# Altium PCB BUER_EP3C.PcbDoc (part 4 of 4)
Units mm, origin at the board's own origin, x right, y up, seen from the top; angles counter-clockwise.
Board outline 150 x 80 mm, 2 copper layers (Top Layer, Bottom Layer), stack 1.571 mm thick; 295 components, 180 nets, 1344 pads, 488 vias.
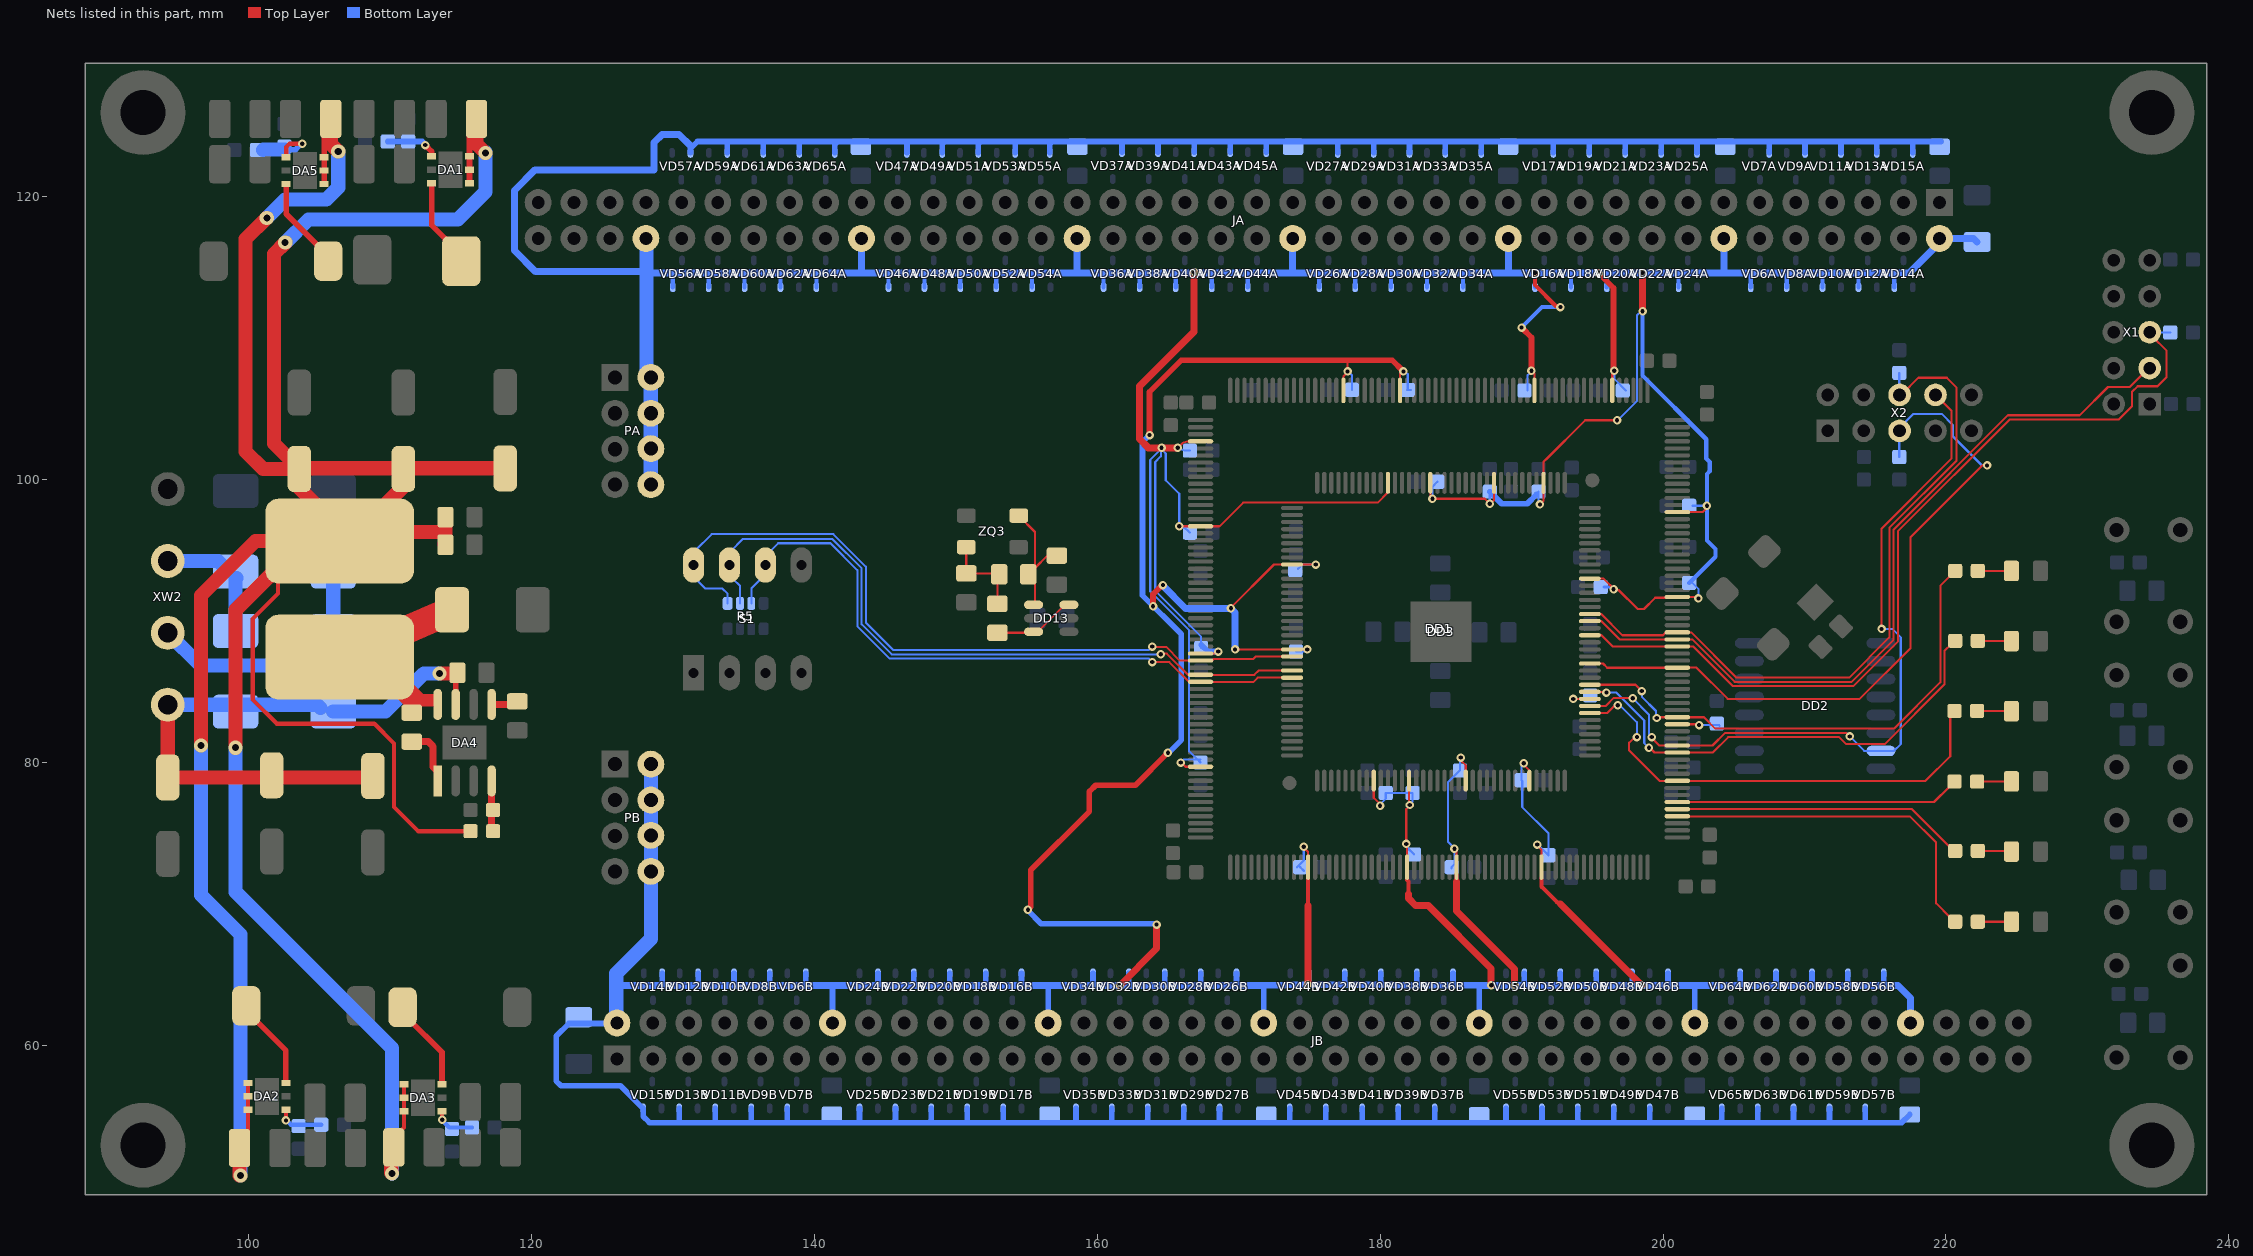
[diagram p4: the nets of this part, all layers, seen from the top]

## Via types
v1: diameter 0.6, hole 0.3, Top Layer to Bottom Layer, tented both sides, 413 vias
v2: diameter 1.4, hole 0.7, Top Layer to Bottom Layer, 32 vias
v3: diameter 1, hole 0.5, Top Layer to Bottom Layer, tented both sides, 19 vias
v4: diameter 0.66, hole 0.33, Top Layer to Bottom Layer, tented top, 16 vias
v5: diameter 0.6, hole 0.3, Top Layer to Bottom Layer, 8 vias

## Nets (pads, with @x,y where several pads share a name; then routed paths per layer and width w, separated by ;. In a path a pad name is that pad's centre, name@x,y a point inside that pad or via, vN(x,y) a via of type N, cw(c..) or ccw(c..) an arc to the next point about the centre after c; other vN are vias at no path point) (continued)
JTAG.TDO: DD1.29 DD3.20 X1.3 | length 54.2
  Top Layer w0.15: DD3.20@194.825,90 195.65,90 196.95,88.7 DD1.29@200.45,88.7 ; DD1.29@201.006,88.707 202.057,88.707 205.064,85.7 213.327,85.7 216.3,88.673 216.3,96.473 224.377,104.55 229.45,104.55 231.45,106.55 233,106.55 X1.3@234.1,107.65
JTAG.TMS: DD1.28 DD3.18 R2.1 X1.5 | length 60.6
  Top Layer w0.15: DD3.18@194.825,89 195.65,89 196.45,88.2 DD1.28@200.3,88.2 ; DD1.28@201.006,88.207 202.133,88.207 204.94,85.4 213.451,85.4 216.6,88.549 216.6,96.349 224.501,104.25 232.22,104.25 233.15,105.18 233.15,106.2 233.55,106.6 234.95,106.6 235.6,107.25 235.6,109.1 X1.5@234.55,110.15
  Bottom Layer w0.15: X1.5@234.4,110.35 234.45,110.4 R2.1@235.85,110.4
LED0: DD1.18 DD3.11 R24.2 | length 35.6
  Top Layer w0.15: DD3.11@194.825,85.5 198.05,85.5 198.3,85.25 198.3,85.1 v1@198.4,85.2 ; v1@199.607,83.207 DD1.18@201.006,83.207 202.89,83.207 203.697,82.4 216.321,82.4 219.6,85.679 219.6,92.5 R24.2@220.3,93.2
  Bottom Layer w0.15: v1(198.5,85.05) 198.5,84.643 199.5,83.642 v1@199.5,83.25
  other v1: 199.55,83.15
LED1: DD1.13 DD3.10 R25.2 | length 33.3
  Top Layer w0.15: DD3.10@194.825,85 195.95,85 v1(196,84.95) ; v1@198.975,81.125 199.025,81.075 199.393,80.707 DD1.13@201.006,80.707 203.507,80.707 204.6,81.8 212.45,81.8 212.925,81.325 215.696,81.325 219.9,85.529 219.9,87.9 R25.2@220.4,88.4
  Bottom Layer w0.15: v1(196,84.95) 196.7,84.95 198.675,82.975 198.675,81.375 v1(199,81.05)
LED2: DD1.9 DD3.7 R26.2 | length 33.6
  Top Layer w0.15: DD3.7@194.825,83.5 196.05,83.5 196.55,84 v1@196.8,84 ; v1@198.1,81.8 198,81.8 197.6,81.4 197.6,80.858 199.751,78.707 DD1.9@201.006,78.707 218.557,78.707 220.3,80.45 R26.2@220.3,83.45
  Bottom Layer w0.15: v1(196.8,84.05) 196.95,84.05 198.15,82.85 v1(198.15,81.8)
LED3: DD1.6 R27.2 | length 19.7
  Top Layer w0.15: DD1.6@201.006,77.207 219.157,77.207 220.25,78.3 R27.2@220.25,78.25
LED4: DD1.5 R28.2 | length 20.7
  Top Layer w0.15: DD1.5@201.006,76.707 217.593,76.707 220.3,74 R28.2@220.6,74
LED5: DD1.4 R29.2 | length 24.8
  Top Layer w0.15: DD1.4@201.006,76.207 201.013,76.2 217.45,76.2 219.3,74.35 219.3,70.05 R29.2@220.3,69.05
MSEL0: DD1.155 DD3.94 R5.1 S1.8 | length 51.1
  Top Layer w0.15: v1@163.9,88 164.075,88.175 164.875,88.175 165.843,87.207 DD1.155@167.306,87.207 ; DD1.155@168.1,87.2 168.225,87.325 171.025,87.325 171.2,87.5 173.25,87.5 DD3.94@173.3,87.55
  Bottom Layer w0.15: S1.8@131.55,94.95 132.75,96.15 141.35,96.15 143.65,93.85 143.65,89.9 145.6,87.95 163.65,87.95 v1(163.9,88.2) ; S1.8@131.7,92.9 132.3,92.3 133.5,92.3 133.875,91.925 R5.1@133.875,91.25
MSEL1: DD1.157 DD3.96 R5.2 S1.7 | length 47.8
  Top Layer w0.15: v1@164.55,87.7 164.926,87.7 166.419,86.207 DD1.157@167.306,86.207 ; DD1.157@167.95,86.2 171.1,86.2 171.4,86.5 DD3.96@173.775,86.5
  Bottom Layer w0.15: S1.7@134.05,94.9 134.95,95.8 141.276,95.8 143.35,93.726 143.35,89.776 145.476,87.65 v1(164.5,87.65) ; S1.7@134.25,93 134.75,92.5 R5.2@134.75,91.25
MSEL2: DD1.158 DD3.97 R5.3 S1.6 | length 45.3
  Top Layer w0.15: v1@163.85,87.1 165.1,87.1 166.493,85.707 DD1.158@167.306,85.707 171.057,85.707 171.35,86 DD3.97@173.2,86
  Bottom Layer w0.15: R5.3@135.55,91.25 135.55,92.3 S1.6@136.2,92.95 ; S1.6@136.75,94.8 137.45,95.5 141.151,95.5 143.05,93.601 143.05,89.624 145.324,87.35 163.65,87.35 v1(163.9,87.1)
NCE: DD1.30 DD3.21 R16.2 X2.6 | length 49.7
  Top Layer w0.15: DD3.21@194.825,90.5 195.626,90.5 197.126,89 200,89 DD1.30@200.2,89.2 ; DD1.30@201.006,89.207 201.981,89.207 205.188,86 213.15,86 216,88.85 216,96.597 220.75,101.347 220.75,106.5 220.05,107.2 218.05,107.2 X2.6@216.9,106.05
  Bottom Layer w0.15: R16.2@216.7,107.55 216.7,105.8 X2.6@216.8,105.7
NCONFIG: DD1.25 DD3.14 R15.1 X2.5 | length 49.5
  Top Layer w0.15: DD3.14@194.825,87 195.75,87 196.05,86.7 DD1.25@200.25,86.7 ; DD1.25@201.006,86.707 202.36,86.707 204.567,84.5 213.9,84.5 217.5,88.1 217.5,95.942 222.558,101 v1(222.9,101)
  Bottom Layer w0.15: R15.1@216.7,101.6 216.7,103.05 X2.5@216.8,103.15 ; X2.5@217.05,104 217.7,104.65 219.7,104.65 220.5,103.85 220.5,103.05 222.55,101 v1(222.9,101)
NCS: DD1.14 DD2.7 DD3.8 X2.8 | length 53.5
  Top Layer w0.15: DD3.8@194.825,84 195.95,84 196.525,84.575 197.825,84.575 v1(197.85,84.55) ; v1@199.175,81.775 199.743,81.207 DD1.14@201.006,81.207 203.499,81.207 204.392,82.1 212.95,82.1 v1@213.175,81.875 ; v1@215.45,89.7 215.45,96.55 220.4,101.5 220.4,104.85 X2.8@219.26,105.99
  Bottom Layer w0.15: v1(197.85,84.55) 199,83.4 199,81.95 v1@199.15,81.8 ; v1(213.2,81.85) 214.225,80.825 DD2.7@215.4,80.825 216.325,80.825 216.8,81.3 216.8,88.85 216.2,89.45 v1@215.35,89.45
  other v1: 199.2,81.8 215.45,89.45
NetC60_1: C60.1 DA4.1 | length 3.4
  Top Layer w0.5: C60.1@111.55,81.475 112.725,81.475 113.05,81.15 113.05,79.7 DA4.1@113.3,79.45
NetC60_2: C60.2 DA4.8 L6.1 VD5.2 | length 15.2
  Top Layer w0.3: L6.1@110.9,85.4 112.19,84.11 DA4.8@113.38,84.11 DA4.8@113.2,84.29 ; L6.1@111.4,85.2 112.075,84.525 ; L6.1@111.6,85.4 112.3,84.7 113.05,84.7 113.2,84.55 DA4.8@113.2,84.29 ; 112.55,84.5 112.525,84.525 112.075,84.525 ; 112.075,84.525 112.2,84.4 113.09,84.4 DA4.8@113.2,84.29
  Top Layer w1: L6.1@109.85,85.9 111.55,84.2 C60.2@111.55,83.525
  Top Layer w2: L6.1@110.75,89.2 VD5.2@114.4,90.8
NetC68_1: C68.1 DA4.5 | length 1.7
  Top Layer w0.5: DA4.5@117.19,84.11 118.81,84.11 C68.1@118.85,84.15
NetC83_1: C83.1 DD13.1 R35.1 ZQ3.1 | length 8.9
  Top Layer w0.15: ZQ3.1@154.45,97.45 155.6,96.3 R35.1@155.6,93.75 ; R35.1@155.45,93.6 R35.1@155.6,93.75 ; DD13.1@155.6,91.15 R35.1@155.6,93.75 ; C83.1@157.15,94.625 156.475,94.625 R35.1@155.6,93.75
NetC84_1: C84.1 R34.1 R35.2 ZQ3.3 | length 6.2
  Top Layer w0.15: C84.1@150.65,93.35 150.744,93.444 ZQ3.3@150.744,95.225 ; C84.1@150.75,93.375 152.925,93.375 R35.2@153,93.3 ; R34.1@152.95,91.225 152.95,93.15 R35.2@153,93.2
NetDA1_1: DA1.1 R6.1 R7.2 | length 3.7
  Top Layer w0.4: v1(112.5,123.65) 112.95,123.2 DA1.1@112.95,122.85
  Bottom Layer w0.4: R6.1@109.85,123.9 R7.2@111.3,123.9 112.3,123.9 v1@112.5,123.7
NetDA1_3: DA1.3 L1.1 | length 4.3
  Top Layer w0.4: DA1.3@112.95,120.95 112.95,118 L1.1@113.9,117.05
NetDA2_1: DA2.1 R8.1 R9.2 | length 3.3
  Top Layer w0.3: v1@102.65,54.75 DA2.1@102.65,55.45
  Bottom Layer w0.3: v1@102.65,54.75 103,54.4 R8.1@105.15,54.4
  other v1: 102.65,54.7
NetDA2_3: DA2.3 L4.1 | length 5.5
  Top Layer w0.4: L4.1@100.4,61.9 102.65,59.65 DA2.3@102.65,57.35
NetDA3_1: DA3.1 R10.1 R11.2 | length 2.9
  Top Layer w0.3: DA3.1@113.68,55.35 113.68,54.82 v1@113.7,54.8
  Bottom Layer w0.3: v1@113.7,54.7 114.2,54.2 R10.1@115.8,54.2
  other v1: 113.7,54.75
NetDA3_3: DA3.3 L5.1 | length 5.7
  Top Layer w0.4: L5.1@111.25,61.95 113.68,59.52 DA3.3@113.68,57.25
NetDA4_4: DA4.4 R12.1 R13.2 | length 3.5
  Top Layer w0.5: R12.1@117.05,75.3 117.19,75.44 DA4.4@117.19,78.7
NetDA5_1: DA5.1 R17.1 R18.2 | length 4.8
  Top Layer w0.3: DA5.1@102.67,122.8 102.67,123.52 102.9,123.75 v1(103.8,123.75)
  Bottom Layer w0.4: R18.2@102.55,123.325 103.325,123.325 v1@103.75,123.75
  Bottom Layer w1: R17.1@101.05,123.3 101.075,123.325 R18.2@102.55,123.325
NetDA5_3: DA5.3 L2.1 | length 5.3
  Top Layer w0.4: DA5.3@102.67,120.9 102.67,118.78 L2.1@104.9,116.55
NetDD1_17: DD1.17 R3.1 | length 3.1
  Top Layer w0.15: DD1.17@201.006,82.707 202.593,82.707 v1@202.6,82.7
  Bottom Layer w0.15: v1(202.55,82.65) 203.95,82.65 R3.1@204,82.6
NetDD3_9: DD3.9 R19.1 | length 2.2
  Top Layer w0.15: v1@193.7,84.5 DD3.9@194.825,84.5
  Bottom Layer w0.15: v1(193.65,84.5) 194.65,84.5 R19.1@194.7,84.55
NetDD13_3: DD13.3 DD13.6 R34.2 | length 5.1
  Top Layer w0.15: R34.2@152.95,89.175 154.975,89.175 DD13.3@155.15,89.35 ; DD13.3@155.5,89.25 155.8,89.25 DD13.6@157.6,91.05
NetLED1_A: LED1.A R24.1 | length 2.4
  Top Layer w0.15: R24.1@222.25,93.55 224.55,93.55 LED1.A@224.6,93.5
NetLED2_A: LED2.A R25.1 | length 2.1
  Top Layer w0.15: R25.1@222.25,88.6 224.3,88.6 LED2.A@224.35,88.55
NetLED3_A: LED3.A R26.1 | length 2.2
  Top Layer w0.15: R26.1@222.2,83.65 224.25,83.65 LED3.A@224.35,83.75
NetLED4_A: LED4.A R27.1 | length 2.4
  Top Layer w0.15: R27.1@222.2,78.65 224.5,78.65 LED4.A@224.6,78.75
NetLED5_A: LED5.A R28.1 | length 2.1
  Top Layer w0.15: R28.1@222.25,73.75 224.25,73.75 LED5.A@224.35,73.65
NetLED6_A: LED6.A R29.1 | length 2.4
  Top Layer w0.15: R29.1@222.25,68.75 224.45,68.75 LED6.A@224.6,68.9
NetVD1_1: VD1.1 VD3.2 XW2.2 | length 7.9
  Bottom Layer w1: XW2.2@94.3,94.25 97.85,94.25 VD3.2@98.25,93.85 ; VD1.1@99.1,89.3 99.1,93 VD3.2@99.15,93.05
NetVD2_1: VD2.1 VD4.2 XW2.3 | length 16.1
  Bottom Layer w1: XW2.3@94.3,89.17 96.62,86.85 103.1,86.85 VD2.1@104.85,88.6 ; VD4.2@106,93.5 106,89.9 VD2.1@106.2,89.7
POWER: C57.1 C59.1 C66.1 C67.1 DA4.7 VD1.2 VD2.2 XW2.4 | length 42.5
  Top Layer w0.4: DA4.7@114.65,84.11 114.65,86.05 C67.1@114.75,86.15
  Top Layer w1: XW2.4@94.55,83.95 94.3,83.7 C59.1@94.3,78.95 108.6,78.95 C66.1@108.8,79.15 ; v3@113.6,86.3 114.725,86.3 C67.1@114.775,86.35
  Bottom Layer w1: XW2.4@94.3,84.09 104.86,84.09 VD2.2@105.1,83.85 ; VD2.2@106,83.6 109.7,83.6 112.4,86.3 v3(113.5,86.3)
VCC: C33.1 C42.1 C51.1 C54.1 C61.1 C62.1 C63.1 C64.1 C65.1 DA1.4 DA1.5 DA1.6 DA2.4 DA2.5 DA2.6 DA3.4 DA3.5 DA3.6 DA5.4 DA5.5 DA5.6 L6.2 R12.2 | length 256.9
  Top Layer w0.3: C51.1@99.75,53.8 99.97,54.02 DA2.6@99.97,55.45 DA2.5@99.97,56.4 DA2.4@99.97,57.35 ; L6.2@102.1,92.9 102.1,91.95 100.3,90.15 100.3,84.45 102,82.75 108.9,82.75 110.3,81.35 110.3,76.85 112,75.15 R12.2@115.7,75.15 ; C54.1@110.65,53.85 111,54.2 DA3.6@111,55.35 DA3.5@111,56.3 DA3.4@111,57.25
  Top Layer w0.4: DA5.4@105.35,120.9 DA5.5@105.35,121.85 DA5.6@105.35,122.8 105.35,124.8 C42.1@105.6,125.05 ; DA1.4@115.63,120.95 DA1.5@115.63,121.9 DA1.6@115.63,122.85 115.63,124.78 C33.1@115.85,125
  Top Layer w1: v3(96.65,81.2) 96.65,91.8 100.5,95.65 L6.2@103.95,95.65 ; v3(99.1,81.05) 99.1,90.8 L6.2@103.95,95.65 ; C51.1@99.375,52.75 99.375,50.8 v3(99.45,50.8) ; v3(101.3,118.5) 99.8,117 99.8,102 101.05,100.75 C63.1@103.6,100.75 101.8,102.55 101.8,115.95 v3(102.6,116.75) ; C63.1@103.45,99.55 106.45,96.55 L6.2@106.45,95.65 ; C63.1@103.55,101 103.75,100.8 C61.1@118.15,100.8 ; C42.1@105.825,125.5 105.825,123.725 v3(106.35,123.2) ; v3@110.1,51 110.1,52.8 C54.1@110.275,52.8 ; C62.1@110.95,99.5 107.1,95.65 L6.2@106.45,95.65 ; L6.2@111.05,96.3 113.925,96.3 ; C65.1@113.85,95.45 113.925,95.525 113.925,96.3 ; C64.1@113.925,97.35 113.925,96.3 ; C33.1@116.125,125.5 116.125,123.725 v3(116.75,123.1) ; L6.2@103.95,95.65 L6.2@106.45,95.65
  Bottom Layer w1: v3(96.65,81.2) 96.65,70.65 99.45,67.85 v3(99.45,50.8) ; v3(99.1,81.05) 99.1,70.85 110.15,59.8 v3(110.15,50.95) ; v3(101.3,118.5) 102.6,119.8 105.5,119.8 106.35,120.65 v3(106.35,123.2) ; v3(102.6,116.75) 104.25,118.4 114.8,118.4 116.75,120.35 v3@116.75,123.15
VIOA: C3.1 C4.1 C5.1 C6.1 C7.1 C8.1 C9.1 C10.1 C36A.1 C37A.1 C38A.1 C39A.1 C40A.1 C41A.1 C46.1 C48.1 C49.1 C50.1 DD1.35 DD1.47 DD1.66 DD1.77 DD1.124 DD1.136 DD1.154 DD1.170 DD3.26 DD3.40 DD3.47 DD3.56 DD3.62 JA.2 JA.14 JA.26 JA.38 JA.50 JA.62 JA.74 PA.2 PA.4 PA.6 PA.8 VD6A.2 VD7A.2 VD8A.2 VD9A.2 VD10A.2 VD11A.2 VD12A.2 VD13A.2 VD14A.2 VD15A.2 VD16A.2 VD17A.2 VD18A.2 VD19A.2 VD20A.2 VD21A.2 VD22A.2 VD23A.2 VD24A.2 VD25A.2 VD26A.2 VD27A.2 VD28A.2 VD29A.2 VD30A.2 VD31A.2 VD32A.2 VD33A.2 VD34A.2 VD35A.2 VD36A.2 VD37A.2 VD38A.2 VD39A.2 VD40A.2 VD41A.2 VD42A.2 VD43A.2 VD44A.2 VD45A.2 VD46A.2 VD47A.2 VD48A.2 VD49A.2 VD50A.2 VD51A.2 VD52A.2 VD53A.2 VD54A.2 VD55A.2 VD56A.2 VD57A.2 VD58A.2 VD59A.2 VD60A.2 VD61A.2 VD62A.2 VD63A.2 VD64A.2 VD65A.2 VD66.2 | length 474
  Top Layer w0.15: v1@165.707,96.707 DD1.136@167.306,96.707 168.657,96.707 170.325,98.375 179.835,98.375 180.55,99.09 DD3.62@180.55,99.1 ; v1@165.8,102.2 cw(c166.162,102.2) 165.906,102.456 165.95,102.5 cw(c166.449,102.001) 166.449,102.707 DD1.124@167.306,102.707 ; v1@165.925,80.025 166.243,79.707 DD1.170@167.306,79.707 ; DD1.154@167.306,87.707 168.307,87.707 v1@168.5,87.9 ; DD3.56@183.55,99.775 183.55,98.9 v1@183.8,98.65 ; v1(183.7,98.65) v1@183.8,98.65 ; v1@183.85,98.6 v1@183.8,98.65 ; v1@187.7,98.35 187.4,98.65 v1@183.8,98.65 ; v1@187.8,98.3 188.05,98.55 DD3.47@188.05,99.775 ; v1@190.65,107.8 190.7,107.75 190.906,107.544 DD1.77@190.906,106.307 ; v1(191.3,98.25) 191.55,98.5 DD3.40@191.55,99.775 191.55,101.258 191.719,101.426 191.726,101.426 194.5,104.2 v1(196.75,104.2) ; DD3.26@195.3,93 195.8,93 196.6,92.2 196.85,92.2 198.2,90.85 198.65,90.85 199.45,91.65 DD1.35@200.15,91.65 ; DD1.66@196.406,106.307 196.406,107.506 196.45,107.55 v1@196.55,107.55 ; DD1.47@200.275,97.675 DD1.47@200.3,97.7 ; DD1.35@201.006,91.707 202.243,91.707 v1@202.3,91.65 ; DD1.47@201.006,97.707 202.807,97.707 v1@203.2,98.1
  Top Layer w0.3: v1(190.95,114.6) 190.95,113.75 192.45,112.25 v1@192.85,112.25
  Top Layer w0.4: v1@190.05,110.7 190.7,110.05 190.7,107.75 v1(190.7,107.7) ; v1(195.45,114.6) 196.5,113.55 v1@196.5,107.75
  Top Layer w0.5: v1(165.7,102.25) v1(164.55,102.25) 163.61,102.25 163,102.86 163,106.6 166.85,110.45 v1(166.85,114.65) ; v1(198.55,111.9) v1(198.55,114.6)
  Bottom Layer w0.15: v1@164.5,102.15 164.5,101.65 164.1,101.25 164.1,92.15 167.35,88.9 167.35,88.325 C7.1@167.35,88.1 ; v1@164.55,102.2 164.15,101.8 163.75,101.4 163.75,92.1 166.5,89.35 166.5,80.8 C8.1@167.075,80.225 ; v1@164.6,102.3 164.6,102.1 164.85,101.85 164.85,99.95 165.8,99 v1(165.8,96.7) ; v1@165.7,96.7 cw(c165.7,95.734) 166.383,96.417 C10.1@166.55,96.25 ; v1@165.8,102.25 ccw(c166.283,102.733) 166.283,102.05 C9.1@166.55,102.05 ; v1(165.9,80) 166.125,80.225 C8.1@167.075,80.225 ; C8.1@167.3,80 C8.1@167.075,80.225 ; C8.1@167.3,80.225 C8.1@167.075,80.225 ; v1(183.7,98.65) 183.7,99.5 C50.1@184.05,99.85 ; C49.1@187.75,99.15 187.75,98.35 v1@187.8,98.3 ; C6.1@190.425,106.3 190.425,107.375 v1@190.7,107.65 ; C48.1@191.2,99.15 191.2,98.35 v1(191.3,98.25) ; v1(196.55,107.7) 196.55,107.125 C5.1@197.375,106.3 ; v1(196.75,104.2) 196.8,104.2 198.15,105.55 198.15,107.05 198.15,111.6 v1@198.45,111.9 ; C3.1@202.075,92.7 202.5,92.275 v1@202.5,91.45 ; C4.1@202.075,98.15 v1(203.1,98.15)
  Bottom Layer w0.2: C46.1@195.825,92.4 196.349,92.4 v1(196.5,92.25)
  Bottom Layer w0.3: 129.9,114.5 130,114.4 VD56A.2@130,113.6 ; VD58A.2@132.537,113.6 132.537,114.538 132.6,114.6 ; 135.05,114.55 135.075,114.525 VD60A.2@135.075,113.6 ; 137.6,114.6 137.612,114.588 VD62A.2@137.612,113.6 ; VD64A.2@140.15,113.6 140.15,114.5 140.25,114.6 ; VD46A.2@145.25,113.6 145.25,114.6 ; VD48A.2@147.787,113.6 147.787,114.488 147.85,114.55 ; VD50A.2@150.325,113.6 150.325,114.525 150.4,114.6 ; 152.85,114.55 152.862,114.538 VD52A.2@152.862,113.6 ; VD54A.2@155.4,113.6 155.4,114.55 ; VD36A.2@160.45,113.6 160.45,114.55 ; VD38A.2@163,113.6 163,114.55 163.05,114.6 ; 165.5,114.55 165.55,114.5 VD40A.2@165.55,113.6 ; VD42A.2@168.1,113.6 168.1,114.45 ; VD44A.2@170.65,113.6 170.65,114.5 170.7,114.55 ; 175.65,114.45 175.7,114.4 VD26A.2@175.7,113.6 ; VD28A.2@178.237,113.6 178.237,114.538 178.25,114.55 ; VD30A.2@180.775,113.6 180.775,114.525 180.8,114.55 ; 183.25,114.45 183.312,114.388 VD32A.2@183.312,113.6 ; VD34A.2@185.85,113.6 185.85,114.6 ; v1(190,110.75) 191.45,112.2 v1(192.75,112.2) ; VD16A.2@190.95,113.6 v1@190.95,114.55 ; VD18A.2@193.487,113.6 193.487,114.538 193.5,114.55 ; VD20A.2@196.025,113.6 196.025,114.475 196.05,114.5 ; v1(198.55,111.9) 198.55,107.35 203.05,102.85 203.05,101.5 203.3,101.25 203.3,100.6 203.1,100.4 203.1,95.7 203.7,95.1 203.7,94.55 C3.1@201.85,92.7 ; VD22A.2@198.562,113.6 198.562,114.562 v1@198.6,114.6 ; VD24A.2@201.1,113.6 201.1,114.55 ; VD6A.2@206.2,113.6 206.2,114.5 ; VD8A.2@208.737,113.6 208.737,114.538 208.75,114.55 ; VD10A.2@211.275,113.6 211.275,114.525 211.35,114.6 ; VD12A.2@213.812,113.6 213.812,114.512 213.85,114.55 ; VD14A.2@216.35,113.6 216.35,114.5 216.4,114.55
  Bottom Layer w0.4: VD57A.2@131.25,123.1 131.25,123.4 131.75,123.9 133.85,123.9 ; VD59A.2@133.85,123.1 133.85,123.9 ; VD61A.2@136.4,123.1 136.4,123.85 ; VD63A.2@138.95,123.1 138.95,123.85 138.9,123.9 ; VD65A.2@141.45,123.1 141.45,123.7 141.5,123.75 ; VD47A.2@146.55,123.1 146.55,123.85 ; VD49A.2@149.05,123.1 149.05,123.75 149.1,123.8 ; VD51A.2@151.6,123.1 151.6,123.75 151.65,123.8 ; VD53A.2@154.2,123.1 154.2,123.8 ; VD55A.2@156.65,123.1 156.65,123.75 156.7,123.8 ; VD37A.2@161.75,123.15 161.75,123.85 161.8,123.9 ; 164.25,123.8 164.3,123.75 VD39A.2@164.3,123.15 ; VD41A.2@166.85,123.15 166.85,123.8 166.9,123.85 ; C7.1@167.35,88.325 167.825,87.85 168.45,87.85 v1@168.5,87.8 ; VD43A.2@169.4,123.15 169.4,123.85 ; VD45A.2@171.95,123.15 171.95,123.8 ; VD27A.2@177,123.1 177,123.85 ; VD29A.2@179.537,123.1 179.537,123.837 179.55,123.85 ; VD31A.2@182.075,123.1 182.075,123.825 182.1,123.85 ; VD33A.2@184.612,123.1 184.612,123.9 ; VD35A.2@187.15,123.1 187.15,123.85 ; C49.1@187.75,99.15 188.6,98.3 190.4,98.3 C48.1@191.05,98.95 ; VD17A.2@192.25,123.1 192.25,123.85 ; 194.75,123.85 194.787,123.813 VD19A.2@194.787,123.1 ; VD21A.2@197.325,123.1 197.325,123.825 197.35,123.85 ; 199.8,123.85 199.862,123.788 VD23A.2@199.862,123.1 ; VD25A.2@202.4,123.1 202.4,123.85 202.35,123.9 ; 207.45,123.85 207.5,123.8 VD7A.2@207.5,123.1 ; VD9A.2@210.037,123.1 210.037,123.837 210.05,123.85 ; VD11A.2@212.575,123.1 212.575,123.825 212.6,123.85 ; VD13A.2@215.112,123.1 215.112,123.812 215.15,123.85 ; VD15A.2@217.65,123.1 217.65,123.9 ; C36A.1@219.65,123.9 217.65,123.9 ; 133.85,123.9 138.9,123.9 ; 138.9,123.9 161.8,123.9 ; 161.8,123.9 184.612,123.9 ; 184.612,123.9 202.35,123.9 ; 202.35,123.9 217.65,123.9
  Bottom Layer w0.5: 128.15,114.7 120.3,114.7 118.8,116.2 118.8,120.45 120.25,121.9 128.681,121.9 128.681,123.831 129.25,124.4 130.45,124.4 131.25,123.6 ; 128.3,114.6 132.6,114.6 137.6,114.6 140.25,114.6 145.25,114.6 150.4,114.6 163.05,114.6 173.8,114.6 ; 143.3,114.65 143.34,114.69 JA.62@143.34,117.05 ; 158.55,114.65 158.58,114.68 JA.50@158.58,117.05 ; JA.38@173.82,117.05 173.82,114.62 173.8,114.6 ; JA.26@189.06,117.05 189.06,114.61 189.05,114.6 ; JA.14@204.3,117.05 204.3,114.7 204.4,114.6 ; JA.2@219.6,116.8 217.4,114.6 211.35,114.6 204.4,114.6 ; JA.2@219.75,116.85 219.95,117.05 221.95,117.05 VD66.2@222.2,116.8 ; 173.8,114.6 185.85,114.6 189.05,114.6 ; 189.05,114.6 v1(190.95,114.6) v1(195.45,114.6) v1(198.55,114.6) 198.6,114.6 204.4,114.6
  Bottom Layer w1: JA.74@128.15,116.7 128.15,114.7 128.15,107.52 128.44,107.23 128.44,99.74 PA.8@128.35,99.65
  other v1: 168.55,87.85 202.5,91.6 187.75,98.3
VIOB: C11.1 C12.1 C13.1 C14.1 C15.1 C16.1 C36B.1 C37B.1 C38B.1 C39B.1 C40B.1 C41B.1 C69.1 C70.1 C71.1 C72.1 C73.1 C74.1 DD1.96 DD1.104 DD1.192 DD1.206 DD1.213 DD1.225 DD3.81 DD3.93 DD3.117 DD3.122 DD3.130 DD3.139 JB.2 JB.14 JB.26 JB.38 JB.50 JB.62 JB.74 PB.2 PB.4 PB.6 PB.8 VD6B.2 VD7B.2 VD8B.2 VD9B.2 VD10B.2 VD11B.2 VD12B.2 VD13B.2 VD14B.2 VD15B.2 VD16B.2 VD17B.2 VD18B.2 VD19B.2 VD20B.2 VD21B.2 VD22B.2 VD23B.2 VD24B.2 VD25B.2 VD26B.2 VD27B.2 VD28B.2 VD29B.2 VD30B.2 VD31B.2 VD32B.2 VD33B.2 VD34B.2 VD35B.2 VD36B.2 VD37B.2 VD38B.2 VD39B.2 VD40B.2 VD41B.2 VD42B.2 VD43B.2 VD44B.2 VD45B.2 VD46B.2 VD47B.2 VD48B.2 VD49B.2 VD50B.2 VD51B.2 VD52B.2 VD53B.2 VD54B.2 VD55B.2 VD56B.2 VD57B.2 VD58B.2 VD59B.2 VD60B.2 VD61B.2 VD62B.2 VD63B.2 VD64B.2 VD65B.2 VD67.2 | length 471.9
  Top Layer w0.15: v1@169.3,90.8 172.5,94 DD3.81@173.775,94 v1(175.45,94) ; v1(169.75,88) DD3.93@173.775,88 v1@174.7,88 ; v1(174.6,74.05) 174.6,74 174.906,73.693 DD1.192@174.906,72.607 ; DD1.104@177.406,106.307 177.406,107.306 v1@177.7,107.6 ; v1(177.7,107.65) 177.7,108.3 177.75,108.35 ; DD3.117@179.55,78.725 179.55,77.5 v1@180.15,76.9 ; DD1.96@181.406,106.307 181.406,107.506 v1@181.6,107.7 ; v1(181.85,74.25) 181.85,76.7 v1@182.05,76.9 ; v1@181.9,74.2 181.906,74.194 DD1.206@181.906,72.607 ; v1@182.05,76.85 v1@182.05,76.9 ; DD3.122@182.05,78.725 v1@182.05,76.9 ; v1@182.15,77 v1@182.05,76.9 ; v1@185.1,74.05 v1(185.25,73.9) 185.406,73.744 DD1.213@185.406,72.607 ; v1@185.65,80.2 186.05,79.8 DD3.130@186.05,78.725 ; v1@190.15,79.85 190.55,79.45 DD3.139@190.55,78.725 ; v1@191,74.25 191.406,73.844 DD1.225@191.406,72.607
  Top Layer w0.3: 174.906,69.85 DD1.192@174.906,72.607 ; DD1.206@181.906,72.607 181.906,71.692 182,71.599 182,70.85 ; 185.4,71.25 DD1.213@185.4,72.1 ; DD1.225@191.4,71.85 191.4,71.227 192.527,70.1 192.65,70.1
  Top Layer w0.4: v1(155.1,69.6) 155.3,69.8 155.3,72.4 159.45,76.55 159.45,77.95 159.9,78.4 162.7,78.4 v1(165,80.7) ; v1@163.7,103.2 163.7,106.2 165.95,108.45 180.85,108.45 181.6,107.7 v1(181.65,107.65) ; v1(163.95,91.05) 163.95,91.9 v1@164.6,92.55
  Top Layer w0.5: v1(161.6,64.25) 164.2,66.85 v1(164.2,68.55) ; v1(174.9,64.3) 174.9,69.9 ; 181.994,70.706 181.994,70.406 182.5,69.9 183.4,69.9 187.85,65.45 v1(187.85,64.25) ; 185.4,71.573 185.4,69.5 189.5,65.4 v1(189.5,64.25) ; 192.75,70 v1(198.5,64.25)
  Bottom Layer w0.15: C73.1@174.05,87.85 174.8,87.85 v1@174.975,88.025 ; C13.1@174.125,72.6 174.6,73.075 v1@174.6,73.95 ; C74.1@174.2,93.7 174.5,94 v1(175.45,94) ; C13.1@174.35,72.6 C13.1@174.617,72.333 ; v1@177.8,107.6 178,107.4 C11.1@178,106.35 ; v1@180,77.05 180.4,77.45 C72.1@180.4,77.85 C69.1@182.25,77.85 ; v1@181.65,107.75 181.952,107.448 C12.1@181.952,106.343 ; v1@181.9,74.15 181.9,74 C15.1@182.4,73.5 ; C12.1@181.907,106.343 C12.1@181.952,106.343 ; v1@182.05,77 182.3,77.25 C69.1@182.3,77.85 ; C12.1@182.177,106.343 C12.1@181.952,106.343 ; C14.1@185.05,72.502 C14.1@185.05,72.6 185.25,72.8 v1@185.25,73.8 ; v1@185.2,74 184.8,74.4 184.8,78.6 C70.1@185.65,79.45 v1@185.65,80.3 ; C71.1@190,78.75 190,79.7 v1@190.15,79.85 ; C71.1@190.05,78.7 190.05,76.85 191.9,75 C16.1@191.9,73.45 191.2,74.15 v1@191.1,74.15
  Bottom Layer w0.4: JB.2@125.45,61.55 122.65,61.55 121.75,60.65 121.75,57.5 122.1,57.15 126.3,57.15 VD15B.2@127.9,55.55 ; VD15B.2@127.9,55.45 127.9,55 128.35,54.55 183.85,54.55 ; 129.2,64.25 129.25,64.3 VD14B.2@129.25,65.1 ; 130.45,54.65 VD13B.2@130.45,55.55 ; 131.75,64.35 131.787,64.387 VD12B.2@131.787,65.1 ; 133,54.6 VD11B.2@133,55.55 ; 134.3,64.4 134.325,64.425 VD10B.2@134.325,65.1 ; 135.55,54.6 VD9B.2@135.55,55.55 ; 136.8,64.4 136.862,64.462 VD8B.2@136.862,65.1 ; 138.1,54.7 VD7B.2@138.1,55.55 ; 139.4,64.4 VD6B.2@139.4,65.1 ; JB.14@141.29,61.59 141.29,64.09 141.3,64.1 ; 143.15,54.65 143.2,54.7 VD25B.2@143.2,55.55 ; 144.4,64.3 144.5,64.4 VD24B.2@144.5,65.1 ; 145.7,54.7 145.737,54.737 VD23B.2@145.737,55.55 ; 146.95,64.35 147.037,64.437 VD22B.2@147.037,65.1 ; 148.25,54.7 148.275,54.725 VD21B.2@148.275,55.55 ; VD20B.2@149.575,65.1 149.575,64.375 149.65,64.3 ; VD19B.2@150.812,55.55 150.812,54.638 150.85,54.6 ; VD18B.2@152.112,65.1 152.112,64.438 152.2,64.35 ; 153.35,54.65 VD17B.2@153.35,55.55 ; 154.6,64.3 154.65,64.35 VD16B.2@154.65,65.1 ; v1(155.1,69.6) 155.1,69.55 156.05,68.6 v1@164.2,68.6 ; JB.26@156.53,61.59 156.53,64.13 156.55,64.15 ; 158.5,54.65 VD35B.2@158.5,55.55 ; VD34B.2@159.7,65.1 159.7,64.4 159.75,64.35 ; VD33B.2@161.037,55.55 161.037,54.663 161.05,54.65 ; VD32B.2@162.237,65.1 162.237,64.313 162.25,64.3 ; 163.55,54.7 163.575,54.725 VD31B.2@163.575,55.55 ; v1(163.7,103.15) 163.2,102.65 163.2,91.819 165.95,89.069 165.95,81.6 v1@165,80.65 ; 164.75,64.35 164.775,64.375 VD30B.2@164.775,65.1 ; 166.1,54.7 166.112,54.712 VD29B.2@166.112,55.55 ; VD28B.2@167.312,65.1 167.312,64.488 167.45,64.35 ; 168.65,54.65 VD27B.2@168.65,55.55 ; 169.85,64.45 VD26B.2@169.85,65.1 ; JB.38@171.77,61.59 171.77,64.22 171.8,64.25 ; 173.6,54.65 VD45B.2@173.6,55.55 ; v1@174.9,64.35 174.95,64.4 VD44B.2@174.95,65.1 ; VD43B.2@176.163,55.55 176.163,54.638 176.2,54.6 ; VD42B.2@177.5,65.1 177.5,64.4 177.55,64.35 ; 178.7,54.65 178.725,54.675 VD41B.2@178.725,55.55 ; VD40B.2@180.05,65.1 180.05,64.45 180.15,64.35 ; 181.25,54.65 181.287,54.687 VD39B.2@181.287,55.55 ; VD38B.2@182.6,65.1 182.6,64.45 182.7,64.35 ; VD37B.2@183.85,55.55 183.85,54.55 ; 185.1,64.35 185.15,64.4 VD36B.2@185.15,65.1 ; 187,64.25 187.01,64.24 JB.50@187.01,61.59 ; 188.9,54.6 VD55B.2@188.9,55.55 ; 190.2,64.25 VD54B.2@190.2,65.1 ; VD53B.2@191.437,55.55 191.437,54.713 191.5,54.65 ; VD52B.2@192.737,65.1 192.737,64.313 192.75,64.3 ; VD51B.2@193.975,55.55 193.975,54.725 194,54.7 ; VD50B.2@195.275,65.1 195.275,64.375 195.4,64.25 ; 196.5,54.6 196.512,54.612 VD49B.2@196.512,55.55 ; VD48B.2@197.812,65.1 197.812,64.388 197.9,64.3 ; 199.05,54.65 VD47B.2@199.05,55.55 ; VD46B.2@200.35,65.1 200.35,64.45 200.4,64.4 ; JB.62@202.25,61.59 202.25,64.15 ; 204.1,54.65 204.15,54.7 VD65B.2@204.15,55.55 ; VD64B.2@205.45,65.1 205.45,64.4 205.5,64.35 ; VD63B.2@206.687,55.55 206.687,54.663 206.7,54.65 ; VD62B.2@207.987,65.1 207.987,64.463 208,64.45 ; 209.2,54.65 209.225,54.675 VD61B.2@209.225,55.55 ; 210.5,64.4 210.525,64.425 VD60B.2@210.525,65.1 ; VD59B.2@211.762,55.55 211.762,54.638 211.8,54.6 ; 213.05,64.25 213.062,64.262 VD58B.2@213.062,65.1 ; 214.25,54.65 214.3,54.7 VD57B.2@214.3,55.55 ; VD56B.2@215.6,65.1 215.6,64.35 215.65,64.3 ; C41B.1@217.45,55.125 216.875,54.55 183.85,54.55
  Bottom Layer w0.5: JB.2@126.05,61.75 126.05,64.15 126.15,64.25 129.2,64.25 v1(161.6,64.25) 171.8,64.25 v1(174.9,64.3) 187,64.25 v1(187.85,64.25) v1(189.5,64.25) 190.2,64.25 195.4,64.25 v1(198.5,64.25) 213.05,64.25 216.6,64.25 217.49,63.36 JB.74@217.49,61.59 ; v1@164.65,92.5 166.25,90.9 v1(169.45,90.9) 169.75,90.6 v1(169.75,88)
  Bottom Layer w1: JB.2@126,61.7 126,65.1 128.45,67.55 PB.8@128.45,72.31 ; PB.2@128.45,79.89 PB.4@128.45,77.35 PB.6@128.45,74.85 128.45,72.5 PB.8@128.5,72.45
  other v1: 191.1,74.2 180,76.95 182.1,77 190.15,79.95 185.7,80.35 174.85,88 164.65,92.55
pads on no net: DD1.144 DD1.171 DD1.173 DD1.174 DD1.175 DD1.176 DD1.177 DD1.237 DD1.238 DD1.239 DD1.240 DD2.3 DD2.4 DD2.5 DD2.6 DD2.11 DD2.12 DD2.13 DD2.14 DD3.146 DD3.147 JA.75 JA.76 JA.77 JA.78 JA.79 JA.80 JB.75 JB.76 JB.77 JB.78 JB.79 JB.80 X1.6 X1.7 X1.8 ZQ3.2 ZQ3.4

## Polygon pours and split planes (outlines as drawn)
1.2V on Bottom Layer "Top Layer-No Net" (hatched 90Degree grid 0.2 track 0.2, remove dead copper, pour order 6): 164.15,67.75 205,67.75 205,111.25 164.15,111.25
GND on Bottom Layer "Top Layer-No Net" (hatched 90Degree grid 0.2 track 0.2, remove dead copper, pour order 7): 182.05,91.5 182.05,87 186.55,87 186.55,91.5 182.05,91.5
GND on Bottom Layer "Top Layer-No Net" (hatched 90Degree grid 0.2 track 0.2, remove dead copper, pour order 8): 88.45,49.45 88.45,129.45 238.45,129.45 238.45,49.45
GND on Top Layer "Top Layer-No Net" (hatched 90Degree grid 0.2 track 0.2, remove dead copper, pour order 9): 88.45,49.45 88.45,129.45 238.45,129.45 238.45,49.45

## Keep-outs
Top Layer:
  circle w0.254: c173.6,78.55 r1
  circle w0.254 net A7: c195,99.95 r1
Keep-Out Layer:
  the board outline again, w0.2

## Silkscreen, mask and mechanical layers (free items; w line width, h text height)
Top Overlay:
  circle w0.228: c143.584,106.763 r0.543
  lines w0.228: 141.414,107.468 142.348,107.583 142.102,106.827 143.041,106.786 ; 142.243,104.918 142.422,105.841 143.065,105.374 143.394,106.254 ; 143.438,107.286 143.186,108.192 ; 143.584,109.044 143.981,108.192 ; 144.009,106.425 144.745,105.841 144.102,105.374 144.925,104.918 ; 144.036,107.063 144.82,107.583 145.066,106.827 145.753,107.468 ; 143.186,108.192 143.584,108.192 143.981,108.192 ; 143.186,108.192 143.981,108.192
  lines w0.254: 143.15,82.1 143.15,82.4 143.5,82.75 147.25,82.75 147.9,83.4 148.55,82.75 152.45,82.75 152.8,82.4 152.8,82.1 ; 143.15,87.45 142.35,87.9 ; 143.15,88.35 142.35,87.9 ; 147.65,84.05 147.65,86.2 145.95,87.9 142.35,87.9
  text "A48" at 146.4,121.65 h1 r90
  text "A46" at 148.9,121.65 h1 r90
  text "A44" at 151.45,121.65 h1 r90
  text "A42" at 154.1,121.65 h1 r90
  text "A40" at 156.6,121.65 h1 r90
  text "GND" at 128.6,121.6 h1 r90
  text "A58" at 131,121.6 h1 r90
  text "A56" at 133.5,121.6 h1 r90
  text "A54" at 136.05,121.6 h1 r90
  text "A52" at 138.7,121.6 h1 r90
  text "A50" at 141.2,121.6 h1 r90
  text "GND" at 143.8,121.6 h1 r90
  text "GND" at 159.05,121.6 h1 r90
  text "A38" at 161.55,121.6 h1 r90
  text "A36" at 164.05,121.6 h1 r90
  text "A34" at 166.6,121.6 h1 r90
  text "A32" at 169.25,121.6 h1 r90
  text "A30" at 171.75,121.6 h1 r90
  text "GND" at 174.25,121.6 h1 r90
  text "A28" at 176.75,121.6 h1 r90
  text "A26" at 179.25,121.6 h1 r90
  text "A24" at 181.8,121.6 h1 r90
  text "A22" at 184.45,121.6 h1 r90
  text "A20" at 186.95,121.6 h1 r90
  text "GND" at 189.6,121.6 h1 r90
  text "A18" at 192,121.6 h1 r90
  text "A16" at 194.5,121.6 h1 r90
  text "A14" at 197.05,121.6 h1 r90
  text "A12" at 199.7,121.6 h1 r90
  text "A10" at 202.2,121.6 h1 r90
  text "GND" at 204.75,121.6 h1 r90
  text "A8" at 207.1,121.6 h1 r90
  text "A6" at 209.6,121.6 h1 r90
  text "A4" at 212.15,121.6 h1 r90
  text "A2" at 214.8,121.6 h1 r90
  text "A0" at 217.3,121.6 h1 r90
  text "JTAG" at 228.6,121.35 h1.2
  text "GND" at 220.05,121.3 h1 r90
  text "A1" at 217.5,113.55 h1 r90
  text "A9" at 207.25,113.25 h1 r90
  text "A7" at 209.9,113.25 h1 r90
  text "A5" at 212.45,113.25 h1 r90
  text "A3" at 215,113.25 h1 r90
  text "A11" at 202.3,112.75 h1 r90
  text "A41" at 156.7,112.6 h1 r90
  text "A51" at 141.3,112.55 h1 r90
  text "A31" at 171.85,112.55 h1 r90
  text "A21" at 187.05,112.55 h1 r90
  text "A19" at 192.1,112.4 h1 r90
  text "A17" at 194.6,112.4 h1 r90
  text "A15" at 197.15,112.4 h1 r90
  text "A13" at 199.8,112.4 h1 r90
  text "A49" at 146.5,112.3 h1 r90
  text "A47" at 149,112.3 h1 r90
  text "A45" at 151.55,112.3 h1 r90
  text "A43" at 154.2,112.3 h1 r90
  text "A59" at 131.1,112.25 h1 r90
  text "A57" at 133.6,112.25 h1 r90
  text "A55" at 136.15,112.25 h1 r90
  text "A53" at 138.8,112.25 h1 r90
  text "A39" at 161.65,112.25 h1 r90
  text "A37" at 164.15,112.25 h1 r90
  text "A35" at 166.7,112.25 h1 r90
  text "A33" at 169.35,112.25 h1 r90
  text "A29" at 176.85,112.25 h1 r90
  text "A27" at 179.35,112.25 h1 r90
  text "A25" at 181.9,112.25 h1 r90
  text "A23" at 184.55,112.25 h1 r90
  text "GND" at 90.65,111.8 h1.52
  text "VIOA" at 128.55,111.4 h1 r90
  text "VIOA" at 143.85,111.4 h1 r90
  text "VIOA" at 159.2,111.4 h1 r90
  text "VIOA" at 174.35,111.4 h1 r90
  text "VIOA" at 189.7,111.4 h1 r90
  text "VIOA" at 204.9,111.4 h1 r90
  text "VIOA" at 220.1,111.4 h1 r90
  text "AC" at 90.65,109.067 h1.52
  text "1.2V" at 130.75,106.7 h1.52
  text "AC" at 90.65,106.333 h1.52
  text "BUER" at 146.65,105.2 h3
  text "1.8V" at 130.75,104.15 h1.52
  text "+V" at 90.65,103.6 h1.52
  text "EP3C" at 146.65,102.4 h2
  text "2.5V" at 130.75,101.6 h1.52
  text "3.3V" at 130.75,99.05 h1.52
  text "AS" at 216.1,98.4 h1.2
  text "1.2V" at 130.5,79.2 h1.52
  text "1.8V" at 130.5,76.65 h1.52
  text "MSEL2" at 150,74.45 h1.52 r90
  text "BUT0" at 152.5,74.45 h1.52 r90
  text "MSEL0" at 145,74.4 h1.52 r90
  text "MSEL1" at 147.45,74.4 h1.52 r90
  text "2.5V" at 130.5,74.1 h1.52
  text "3.3V" at 130.5,71.55 h1.52
  text "B11" at 144.45,63.6 h1 r90
  text "B13" at 146.9,63.6 h1 r90
  text "B15" at 149.45,63.6 h1 r90
  text "B17" at 152,63.6 h1 r90
  text "B19" at 154.55,63.6 h1 r90
  text "B21" at 159.6,63.6 h1 r90
  text "B23" at 162.05,63.6 h1 r90
  text "B25" at 164.6,63.6 h1 r90
  text "B27" at 167.15,63.6 h1 r90
  text "B29" at 169.7,63.6 h1 r90
  text "B31" at 174.9,63.6 h1 r90
  text "B33" at 177.35,63.6 h1 r90
  text "B35" at 179.9,63.6 h1 r90
  text "B37" at 182.45,63.6 h1 r90
  text "B39" at 185,63.6 h1 r90
  text "B51" at 205.4,63.6 h1 r90
  text "B53" at 207.85,63.6 h1 r90
  text "B55" at 210.4,63.6 h1 r90
  text "B57" at 212.95,63.6 h1 r90
  text "B59" at 215.5,63.6 h1 r90
  text "B41" at 190.15,63.55 h1 r90
  text "B43" at 192.6,63.55 h1 r90
  text "B45" at 195.15,63.55 h1 r90
  text "B47" at 197.7,63.55 h1 r90
  text "B49" at 200.25,63.55 h1 r90
  text "B1" at 129.1,63.45 h1 r90
  text "B3" at 131.55,63.45 h1 r90
  text "B5" at 134.1,63.45 h1 r90
  text "B7" at 136.65,63.45 h1 r90
  text "B9" at 139.25,63.45 h1 r90
  text "VIOB" at 126.65,63.3 h1 r90
  text "VIOB" at 141.9,63.3 h1 r90
  text "VIOB" at 187.65,63.3 h1 r90
  text "VIOB" at 218.15,63.3 h1 r90
  text "VIOB" at 157.15,63.25 h1 r90
  text "VIOB" at 172.4,63.25 h1 r90
  text "VIOB" at 202.9,63.25 h1 r90
  text "B0" at 129.15,55.4 h1 r90
  text "B2" at 131.6,55.4 h1 r90
  text "B4" at 134.15,55.4 h1 r90
  text "B6" at 136.7,55.4 h1 r90
  text "B8" at 139.3,55.4 h1 r90
  text "GND" at 141.85,54.75 h1 r90
  text "B10" at 144.4,54.6 h1 r90
  text "B12" at 146.9,54.6 h1 r90
  text "B14" at 149.45,54.6 h1 r90
  text "B16" at 152,54.6 h1 r90
  text "B18" at 154.6,54.6 h1 r90
  text "B34" at 179.9,54.45 h1 r90
  text "B36" at 182.45,54.45 h1 r90
  text "B38" at 185.05,54.45 h1 r90
  text "GND" at 126.5,54.4 h1 r90
  text "GND" at 157.05,54.4 h1 r90
  text "B20" at 159.7,54.4 h1 r90
  text "B22" at 162.3,54.4 h1 r90
  text "B24" at 164.75,54.4 h1 r90
  text "B26" at 167.3,54.4 h1 r90
  text "B28" at 169.85,54.4 h1 r90
  text "GND" at 172.2,54.4 h1 r90
  text "B30" at 174.8,54.4 h1 r90
  text "B32" at 177.3,54.4 h1 r90
  text "GND" at 187.55,54.4 h1 r90
  text "B40" at 190.1,54.4 h1 r90
  text "B42" at 192.55,54.4 h1 r90
  text "B44" at 195.1,54.4 h1 r90
  text "B46" at 197.65,54.4 h1 r90
  text "B48" at 200.25,54.4 h1 r90
  text "GND" at 202.7,54.4 h1 r90
  text "B50" at 205.3,54.4 h1 r90
  text "B52" at 207.75,54.4 h1 r90
  text "B54" at 210.3,54.4 h1 r90
  text "B56" at 212.85,54.4 h1 r90
  text "B58" at 215.45,54.4 h1 r90
  text "GND" at 218,54.4 h1 r90
Mechanical 1:
  lines w0.254: 198.884,74.325 199.203,74.644
Mechanical 2:
  lines w0.254: 167.233,74.718 167.233,104.192 169.377,106.337 198.903,106.337 201.069,104.171 201.069,74.714 198.887,72.532 169.418,72.532 167.233,74.718
Mechanical 3:
  lines w0.254: 164.15,67.75 205,67.75 205,111.25 164.15,111.25 164.15,67.75

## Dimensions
88.45,49.45 to 88.45,129.45 on Mechanical 1
88.45,49.45 to 238.45,49.45 on Mechanical 1
92.55,52.95 to 234.55,52.95 on Mechanical 1
92.55,125.95 to 92.55,52.95 on Mechanical 1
